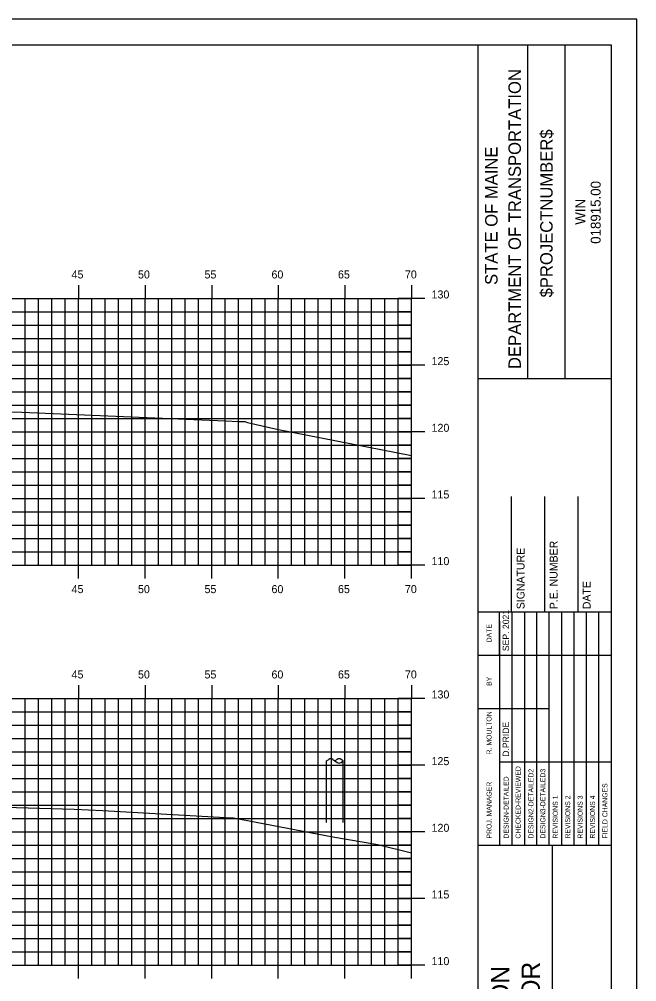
# Model space of a CAD drawing. Extents: x 852847 to 853019, y 365624 to 365734.
# Drawn here: x 852970.9 to 853017.2, y 365661.8 to 365734 of the extents above; entities that cross this region are included whole.
import ezdxf

# ---------------------------------------------------------------- set-up
doc = ezdxf.new("R2010")
doc.units = 0
for name, color, linetype in [('BORDER', 7, 'Continuous'), ('H_V ANNOTATION', 7, 'Continuous'), ('M_Roadway_Centerline', 7, 'Continuous'), ('MAJOR', 7, 'Continuous'), ('MINOR', 7, 'Continuous'), ('PLOT BOUNDARY', 7, 'Continuous'), ('S_Roadway_Centerline', 7, 'Continuous'), ('S_Utilities_Pole_StreetLight', 7, 'Continuous')]:
    doc.layers.add(name, color=color, linetype=linetype)

msp = doc.modelspace()

# ---------------------------------------------------------------- linework, layer by layer
at = {"layer": 'BORDER'}
for p, q in [((853005.305, 365627.027), (853005.305, 365732.027)), ((853009.034, 365707.024), (853009.034, 365732.024)), ((853011.829, 365707.024), (853011.829, 365732.024)), ((853005.306, 365707.021), (853015.305, 365707.021)), ((853007.805, 365689.53), (853007.805, 365698.177)), ((853010.305, 365689.53), (853010.305, 365698.177)), ((853012.805, 365689.53), (853012.805, 365698.177)), ((853005.305, 365689.53), (853015.305, 365689.53)), ((853005.305, 365672.03), (853015.305, 365672.03)), ((853010.896, 365637.03), (853010.896, 365672.03))]:
    msp.add_line(p, q, dxfattribs=at)
msp.add_lwpolyline([(852855.305, 365627.027), (853015.305, 365627.027), (853015.305, 365732.027), (852855.305, 365732.027)], close=True, dxfattribs=at)
for points in [[(853006.92, 365686.28), (853006.92, 365689.53)], [(853007.853, 365672.033), (853007.853, 365689.53)], [(853008.784, 365689.53), (853008.784, 365672.033)], [(853009.716, 365672.033), (853009.716, 365689.53)], [(853010.648, 365672.033), (853010.648, 365689.53)], [(853011.579, 365672.033), (853011.579, 365689.53)], [(853012.511, 365672.033), (853012.511, 365689.53)], [(853013.443, 365672.033), (853013.443, 365689.53)], [(853014.374, 365672.033), (853014.374, 365689.53)], [(853006.921, 365672.033), (853006.921, 365688.824)], [(853005.305, 365686.28), (853015.305, 365686.28)], [(853005.305, 365682.28), (853006.921, 365682.28)], [(853006.92, 365682.28), (853010.647, 365682.28)], [(853006.92, 365678.28), (853015.305, 365678.28)]]:
    msp.add_lwpolyline(points, dxfattribs=at)
at = {"layer": 'MAJOR'}
for p, q in [((852975.305, 365714.029), (852975.305, 365713.027)), ((852980.305, 365714.029), (852980.305, 365713.027)), ((852985.305, 365714.029), (852985.305, 365713.027)), ((852990.305, 365714.029), (852990.305, 365713.027)), ((852995.305, 365714.029), (852995.305, 365713.027)), ((853000.305, 365714.029), (853000.305, 365713.027)), ((852860.305, 365713.027), (853000.305, 365713.027)), ((852860.305, 365713.027), (853000.305, 365713.027)), ((852975.305, 365693.027), (852975.305, 365713.027)), ((852980.305, 365693.027), (852980.305, 365713.027)), ((852985.305, 365693.027), (852985.305, 365713.027)), ((852990.305, 365693.027), (852990.305, 365713.027)), ((852995.305, 365693.027), (852995.305, 365713.027)), ((853001.307, 365713.027), (852999.303, 365713.027)), ((853000.305, 365693.027), (853000.305, 365713.027)), ((853000.305, 365693.027), (853000.305, 365713.027)), ((852860.305, 365708.027), (853000.305, 365708.027)), ((853001.307, 365708.027), (852999.303, 365708.027)), ((852860.305, 365703.027), (853000.305, 365703.027)), ((853001.307, 365703.027), (852999.303, 365703.027)), ((852860.305, 365698.027), (853000.305, 365698.027)), ((853001.307, 365698.027), (852999.303, 365698.027)), ((852860.305, 365693.027), (853000.305, 365693.027)), ((852860.305, 365693.027), (853000.305, 365693.027)), ((852975.305, 365692.025), (852975.305, 365693.027)), ((852980.305, 365692.025), (852980.305, 365693.027)), ((852985.305, 365692.025), (852985.305, 365693.027)), ((852990.305, 365692.025), (852990.305, 365693.027)), ((852995.305, 365692.025), (852995.305, 365693.027)), ((853001.307, 365693.027), (852999.303, 365693.027)), ((853000.305, 365692.025), (853000.305, 365693.027)), ((852975.305, 365684.029), (852975.305, 365683.027)), ((852980.305, 365684.029), (852980.305, 365683.027)), ((852985.305, 365684.029), (852985.305, 365683.027)), ((852990.305, 365684.029), (852990.305, 365683.027)), ((852995.305, 365684.029), (852995.305, 365683.027)), ((853000.305, 365684.029), (853000.305, 365683.027)), ((852860.305, 365683.027), (853000.305, 365683.027)), ((852860.305, 365683.027), (853000.305, 365683.027)), ((852975.305, 365663.027), (852975.305, 365683.027)), ((852980.305, 365663.027), (852980.305, 365683.027)), ((852985.305, 365663.027), (852985.305, 365683.027)), ((852990.305, 365663.027), (852990.305, 365683.027)), ((852995.305, 365663.027), (852995.305, 365683.027)), ((853001.307, 365683.027), (852999.303, 365683.027)), ((853000.305, 365663.027), (853000.305, 365683.027)), ((853000.305, 365663.027), (853000.305, 365683.027)), ((852860.305, 365678.027), (853000.305, 365678.027)), ((853001.307, 365678.027), (852999.303, 365678.027)), ((852860.305, 365673.027), (853000.305, 365673.027)), ((853001.307, 365673.027), (852999.303, 365673.027)), ((852860.305, 365668.027), (853000.305, 365668.027)), ((853001.307, 365668.027), (852999.303, 365668.027)), ((852860.305, 365663.027), (853000.305, 365663.027)), ((852860.305, 365663.027), (853000.305, 365663.027)), ((852975.305, 365662.025), (852975.305, 365663.027)), ((852980.305, 365662.025), (852980.305, 365663.027)), ((852985.305, 365662.025), (852985.305, 365663.027)), ((852990.305, 365662.025), (852990.305, 365663.027)), ((852995.305, 365662.025), (852995.305, 365663.027)), ((853001.307, 365663.027), (852999.303, 365663.027)), ((853000.305, 365662.025), (853000.305, 365663.027))]:
    msp.add_line(p, q, dxfattribs=at)
at = {"layer": 'MINOR'}
for p, q in [((852971.305, 365693.027), (852971.305, 365713.027)), ((852972.305, 365693.027), (852972.305, 365713.027)), ((852973.305, 365693.027), (852973.305, 365713.027)), ((852974.305, 365693.027), (852974.305, 365713.027)), ((852976.305, 365693.027), (852976.305, 365713.027)), ((852977.305, 365693.027), (852977.305, 365713.027)), ((852978.305, 365693.027), (852978.305, 365713.027)), ((852979.305, 365693.027), (852979.305, 365713.027)), ((852981.305, 365693.027), (852981.305, 365713.027)), ((852982.305, 365693.027), (852982.305, 365713.027)), ((852983.305, 365693.027), (852983.305, 365713.027)), ((852984.305, 365693.027), (852984.305, 365713.027)), ((852986.305, 365693.027), (852986.305, 365713.027)), ((852987.305, 365693.027), (852987.305, 365713.027)), ((852988.305, 365693.027), (852988.305, 365713.027)), ((852989.305, 365693.027), (852989.305, 365713.027)), ((852991.305, 365693.027), (852991.305, 365713.027)), ((852992.305, 365693.027), (852992.305, 365713.027)), ((852993.305, 365693.027), (852993.305, 365713.027)), ((852994.305, 365693.027), (852994.305, 365713.027)), ((852996.305, 365693.027), (852996.305, 365713.027)), ((852997.305, 365693.027), (852997.305, 365713.027)), ((852998.305, 365693.027), (852998.305, 365713.027)), ((852999.305, 365693.027), (852999.305, 365713.027)), ((852860.305, 365712.027), (853000.305, 365712.027)), ((853000.305, 365712.027), (852999.303, 365712.027)), ((852860.305, 365711.027), (853000.305, 365711.027)), ((853000.305, 365711.027), (852999.303, 365711.027)), ((852860.305, 365710.027), (853000.305, 365710.027)), ((853000.305, 365710.027), (852999.303, 365710.027)), ((852860.305, 365709.027), (853000.305, 365709.027)), ((853000.305, 365709.027), (852999.303, 365709.027)), ((852860.305, 365707.027), (853000.305, 365707.027)), ((853000.305, 365707.027), (852999.303, 365707.027)), ((852860.305, 365706.027), (853000.305, 365706.027)), ((853000.305, 365706.027), (852999.303, 365706.027)), ((852860.305, 365705.027), (853000.305, 365705.027)), ((853000.305, 365705.027), (852999.303, 365705.027)), ((852860.305, 365704.027), (853000.305, 365704.027)), ((853000.305, 365704.027), (852999.303, 365704.027)), ((852860.305, 365702.027), (853000.305, 365702.027)), ((853000.305, 365702.027), (852999.303, 365702.027)), ((852860.305, 365701.027), (853000.305, 365701.027)), ((853000.305, 365701.027), (852999.303, 365701.027)), ((852860.305, 365700.027), (853000.305, 365700.027)), ((853000.305, 365700.027), (852999.303, 365700.027)), ((852860.305, 365699.027), (853000.305, 365699.027)), ((853000.305, 365699.027), (852999.303, 365699.027)), ((852860.305, 365697.027), (853000.305, 365697.027)), ((853000.305, 365697.027), (852999.303, 365697.027)), ((852860.305, 365696.027), (853000.305, 365696.027)), ((853000.305, 365696.027), (852999.303, 365696.027)), ((852860.305, 365695.027), (853000.305, 365695.027)), ((853000.305, 365695.027), (852999.303, 365695.027)), ((852860.305, 365694.027), (853000.305, 365694.027)), ((853000.305, 365694.027), (852999.303, 365694.027)), ((852971.305, 365663.027), (852971.305, 365683.027)), ((852972.305, 365663.027), (852972.305, 365683.027)), ((852973.305, 365663.027), (852973.305, 365683.027)), ((852974.305, 365663.027), (852974.305, 365683.027)), ((852976.305, 365663.027), (852976.305, 365683.027)), ((852977.305, 365663.027), (852977.305, 365683.027)), ((852978.305, 365663.027), (852978.305, 365683.027)), ((852979.305, 365663.027), (852979.305, 365683.027)), ((852981.305, 365663.027), (852981.305, 365683.027)), ((852982.305, 365663.027), (852982.305, 365683.027)), ((852983.305, 365663.027), (852983.305, 365683.027)), ((852984.305, 365663.027), (852984.305, 365683.027)), ((852986.305, 365663.027), (852986.305, 365683.027)), ((852987.305, 365663.027), (852987.305, 365683.027)), ((852988.305, 365663.027), (852988.305, 365683.027)), ((852989.305, 365663.027), (852989.305, 365683.027)), ((852991.305, 365663.027), (852991.305, 365683.027)), ((852992.305, 365663.027), (852992.305, 365683.027)), ((852993.305, 365663.027), (852993.305, 365683.027)), ((852994.305, 365663.027), (852994.305, 365683.027)), ((852996.305, 365663.027), (852996.305, 365683.027)), ((852997.305, 365663.027), (852997.305, 365683.027)), ((852998.305, 365663.027), (852998.305, 365683.027)), ((852999.305, 365663.027), (852999.305, 365683.027)), ((852860.305, 365682.027), (853000.305, 365682.027)), ((853000.305, 365682.027), (852999.303, 365682.027)), ((852860.305, 365681.027), (853000.305, 365681.027)), ((853000.305, 365681.027), (852999.303, 365681.027)), ((852860.305, 365680.027), (853000.305, 365680.027)), ((853000.305, 365680.027), (852999.303, 365680.027)), ((852860.305, 365679.027), (853000.305, 365679.027)), ((853000.305, 365679.027), (852999.303, 365679.027)), ((852860.305, 365677.027), (853000.305, 365677.027)), ((853000.305, 365677.027), (852999.303, 365677.027)), ((852860.305, 365676.027), (853000.305, 365676.027)), ((853000.305, 365676.027), (852999.303, 365676.027)), ((852860.305, 365675.027), (853000.305, 365675.027)), ((853000.305, 365675.027), (852999.303, 365675.027)), ((852860.305, 365674.027), (853000.305, 365674.027)), ((853000.305, 365674.027), (852999.303, 365674.027)), ((852860.305, 365672.027), (853000.305, 365672.027)), ((853000.305, 365672.027), (852999.303, 365672.027)), ((852860.305, 365671.027), (853000.305, 365671.027)), ((853000.305, 365671.027), (852999.303, 365671.027)), ((852860.305, 365670.027), (853000.305, 365670.027)), ((853000.305, 365670.027), (852999.303, 365670.027)), ((852860.305, 365669.027), (853000.305, 365669.027)), ((853000.305, 365669.027), (852999.303, 365669.027)), ((852860.305, 365667.027), (853000.305, 365667.027)), ((853000.305, 365667.027), (852999.303, 365667.027)), ((852860.305, 365666.027), (853000.305, 365666.027)), ((853000.305, 365666.027), (852999.303, 365666.027)), ((852860.305, 365665.027), (853000.305, 365665.027)), ((853000.305, 365665.027), (852999.303, 365665.027)), ((852860.305, 365664.027), (853000.305, 365664.027)), ((853000.305, 365664.027), (852999.303, 365664.027))]:
    msp.add_line(p, q, dxfattribs=at)
at = {"layer": 'PLOT BOUNDARY'}
msp.add_lwpolyline([(852847.212, 365623.968), (853017.212, 365623.968), (853017.212, 365733.968), (852847.212, 365733.968)], close=True, dxfattribs=at)
at = {"layer": 'S_Roadway_Centerline'}
for points in [[(852923.423, 365702.524), (852930.953, 365703.18), (852932.624, 365703.299), (852942.124, 365704.007), (852950.47, 365704.305), (852952.545, 365704.368), (852956.79, 365704.525), (852962.095, 365704.551), (852969.654, 365704.522), (852971.063, 365704.511), (852986.326, 365703.852), (852987.344, 365703.811), (852987.79, 365703.787), (852988, 365703.722), (852990.182, 365703.23), (853000.305, 365701.246)], [(852918.469, 365672.292), (852926.799, 365673.154), (852937.922, 365673.922), (852939.535, 365674.03), (852939.906, 365674.06), (852940.215, 365674.084), (852941.397, 365674.18), (852944.138, 365674.402), (852946.198, 365674.474), (852955.457, 365674.78), (852958.961, 365674.891), (852961.401, 365674.889), (852963.083, 365674.897), (852965.393, 365674.916), (852968.724, 365674.924), (852968.893, 365674.908), (852974.97, 365674.735), (852977.127, 365674.63), (852986.317, 365674.095), (852986.928, 365674.078), (852994.385, 365672.658), (852997.766, 365672.075), (853000.305, 365671.445)]]:
    msp.add_lwpolyline(points, dxfattribs=at)
at = {"layer": 'S_Utilities_Pole_StreetLight'}
for p, q in [((852993.931, 365673.721), (852993.928, 365678.341)), ((852993.931, 365678.341), (852994.088, 365678.451)), ((852994.4, 365678.451), (852994.556, 365678.341)), ((852994.713, 365678.451), (852994.556, 365678.341)), ((852994.556, 365678.341), (852994.713, 365678.23)), ((852995.181, 365678.341), (852995.025, 365678.451)), ((852995.025, 365678.23), (852995.181, 365678.341)), ((852995.181, 365673.721), (852995.178, 365678.341))]:
    msp.add_line(p, q, dxfattribs=at)
for centre, start, end in [((852994.244, 365678.23), 90, 125.26439), ((852994.244, 365678.23), 54.73561, 90), ((852994.869, 365678.23), 90, 125.26439), ((852994.869, 365678.451), 234.73561, 270), ((852994.869, 365678.23), 54.73561, 90), ((852994.869, 365678.451), 270, 305.26439)]:
    msp.add_arc(centre, 0.271, start, end, dxfattribs=at)

# ---------------------------------------------------------------- texts
at = {"layer": 'BORDER'}
for s, height, p in [('DEPARTMENT OF TRANSPORTATION', 0.93176, (853008.512, 365707.733)), ('$PROJECTNUMBER$', 0.93176, (853010.897, 365713.106)), ('STATE OF MAINE', 0.93176, (853006.76, 365714.039)), ('018915.00', 0.7453, (853014.501, 365717.125)), ('WIN', 0.7453, (853013.342, 365718.557)), ('P.E. NUMBER', 0.59055, (853011.266, 365689.722)), ('SIGNATURE', 0.5906, (853008.786, 365689.722)), ('DATE', 0.5906, (853013.746, 365689.722)), ('SEP. 2021', 0.4845, (853007.628, 365686.575)), ('DATE', 0.3714, (853006.309, 365687.235)), ('BY', 0.3714, (853006.309, 365683.965)), ('R. MOULTON', 0.3727, (853006.309, 365678.832)), ('D.PRIDE', 0.4845, (853007.628, 365678.653)), ('CHECKED-REVIEWED', 0.37275, (853008.486, 365672.518)), ('DESIGN2-DETAILED2', 0.37275, (853009.455, 365672.518)), ('DESIGN3-DETAILED3', 0.37275, (853010.349, 365672.518)), ('DESIGN-DETAILED', 0.37275, (853007.592, 365672.518)), ('PROJ. MANAGER', 0.37275, (853006.309, 365672.518)), ('FIELD CHANGES', 0.37275, (853015.008, 365672.518)), ('REVISIONS 1', 0.37275, (853011.281, 365672.518)), ('REVISIONS 2', 0.37275, (853012.213, 365672.518)), ('REVISIONS 3', 0.37275, (853013.145, 365672.518)), ('REVISIONS 4', 0.37275, (853014.076, 365672.518)), ('I-395/ROUTE 9 CONNECTOR', 1.37787, (853009.94, 365638.192)), ('BREWER TO EDDINGTON', 1.37787, (853007.639, 365640.231))]:
    msp.add_text(s, height=height, rotation=90, dxfattribs=at).set_placement(p)
at = {"layer": 'H_V ANNOTATION'}
for s, p in [('45', (852974.783, 365714.527)), ('50', (852979.77, 365714.527)), ('55', (852984.762, 365714.527)), ('60', (852989.791, 365714.527)), ('65', (852994.783, 365714.527)), ('70', (852999.807, 365714.527)), ('130', (853001.805, 365713.027)), ('125', (853001.805, 365708.027)), ('120', (853001.805, 365703.027)), ('115', (853001.805, 365698.027)), ('110', (853001.805, 365693.027)), ('45', (852974.783, 365690.927)), ('50', (852979.77, 365690.927)), ('55', (852984.762, 365690.927)), ('60', (852989.791, 365690.927)), ('65', (852994.783, 365690.927)), ('70', (852999.807, 365690.927)), ('45', (852974.783, 365684.527)), ('50', (852979.77, 365684.527)), ('55', (852984.762, 365684.527)), ('60', (852989.791, 365684.527)), ('65', (852994.783, 365684.527)), ('70', (852999.807, 365684.527)), ('130', (853001.805, 365683.027)), ('125', (853001.805, 365678.027)), ('120', (853001.805, 365673.027)), ('115', (853001.805, 365668.027)), ('110', (853001.805, 365663.027))]:
    msp.add_text(s, height=0.6, dxfattribs=at).set_placement(p)
at = {"layer": 'M_Roadway_Centerline'}
for s, p in [('C', (852971.058, 365704.511)), ('L', (852971.063, 365704.503))]:
    msp.add_text(s, height=0.0146, dxfattribs=at).set_placement(p)

doc.saveas('drawing.dxf')
